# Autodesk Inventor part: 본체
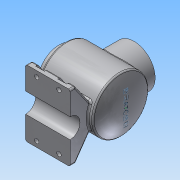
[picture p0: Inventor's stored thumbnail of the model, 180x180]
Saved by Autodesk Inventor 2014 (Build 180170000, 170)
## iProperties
Created: 2017-04
Part Number: 본체
Material: 알루미늄 6061
Document SubType Name: Modeling
Designer: NET
Density: 2.71 g/cm^3
Appearance: 알루미늄 - 평지
Author: NET
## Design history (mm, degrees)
sketch "스케치1"
  geometry: L1 (0, 0)-(0, 38); L2 (0, 38)-(12, 38); L3 (12, 38)-(12, 50); L4 (12, 50)-(110.934, 50); L5 (120, 5.651)-(120, 0); L6 (120, 0)-(0, 0); L7 (0, 27)-(22, 27); L8 (22, 27)-(22, 40); L9 (22, 40)-(104.104, 40); L10 (110, 5.651)-(110, 0); L11 (62, 73.5)-(62, 0); L12 (62, 73.5)-(100, 73.5); L13 (100, 73.5)-(100, 30.802); L14 (100, 30.802)-(62, 30.802); L15 (89, 73.5)-(89, 30.802); L16 (62, 0)-(62, -72); L17 (62, -72)-(102, -72); L18 (102, -72)-(102, -82); L19 (102, -82)-(62, -82); L20 (62, -82)-(62, -72); L21 (62, -72)-(22, -72); L22 (22, -72)-(22, -82); L23 (22, -82)-(62, -82); A1 r 113 centre (7, 5.651) between (119.859, 0) and (110.934, 50); A2 r 103 centre (7, 5.651) between (109.871, 0.5) and (104.104, 40); 1 further point
  constraints: 46 end point, 14 perpendicular, 7 parallel, 7 point on line, 6 point on circle, 2 centre point, 2 tangent, 2 vertical, 1 collinear, 1 midpoint
  dimensions: "d0" = 54 diameter of L7 L6; "d1" = 76 diameter of L2 L6; "d2" = 100 diameter of L4 L6; "d3" = 80 diameter of L9 L6; "d4" = 12 distance between parallel lines of L3 L1; "d5" = 22 distance between parallel lines of L8 L1; "d7" = 226 diameter of A1; "d8" = 10 radial gap between concentric circles of A2 A1; "d45" = 50 distance between parallel lines of L3 L11; "d46" = 23.5 distance between parallel lines of L4 L12; "d47" = 76 diameter of L13 L11; "d48" = 54 diameter of L15 L11; "d49" = 80 distance between parallel lines of L18 L22; "d50" = 10 distance between parallel lines of L21 L23; "d127" = 108 horizontal distance of L3.end L5.end; "d136" = 82 distance from line of L19 L10.end
revolve "회전1" stored, may be unused: angle "d14" = 90 deg
sketch "스케치3"
  geometry: C1 r 38 at (0, 0) reference; A1 r 32.5 centre (0, 0) between (0, 32.5) and (-32.5, 0); 2 further points
  constraints: 4 point on circle, 1 centre point, 1 coincident
  dimensions: "d28" = 65 diameter of A1
hole "구멍1" sketch "스케치3" at (-32.5, 0), (32.5, 0), (0, 32.5), (0, -32.5) diameter "d29" = 3.242; stored, may be unused: countersink angle "d33" = 90 deg, drill point angle "d35" = 118 deg; dims "d30" = 8, "d31" = 4, "d32" = 2, "d34" = 10
revolve "회전3" stored, may be unused: angle "d51" = 90 deg
extrude "돌출4" join sketch "스케치1" stored distance "d52" = 120; taper "d53" = 0 deg
sketch "스케치5"
  geometry: L1 (-120, 0)-(0, 0) reference; L2 (-120, 10)-(0, 10) reference; L3 (-120, 0)-(-120, 10) reference; L4 (-120, 10)-(-70.771, 44.47); L5 (-70.771, 44.47)-(-49.229, 44.47); L6 (-49.229, 44.47)-(0, 10); C1 r 18 at (-60, 0); 1 further point
  constraints: 6 end point, 1 centre point, 1 equal length, 1 midpoint, 1 perpendicular
  dimensions: "d54" = 55 deg angle of L3 L4; "d55" = 36 diameter of C1
extrude "돌출5" join sketch "스케치5" distance "d56" = 80; taper "d57" = 0 deg
extrude "돌출6" cut sketch "스케치5" distance "d58" = 80; taper "d59" = 0 deg
node "작업 평면1"
sketch "스케치6"
  geometry: L1 (40, 0)-(-40, 0) reference; L2 (-40, -78)-(-40, -120) reference; L3 (-40, 0)-(-40, -42) reference; L4 (40, 0)-(40, -42) reference; L5 (40, -78)-(40, -120) reference; L6 (-40, -120)-(40, -120) reference; L7 (-28, -10)-(-28, 0); L8 (-12, -10)-(-12, 0); L9 (12, -10)-(12, 0); L10 (28, -10)-(28, 0); L11 (12, -110)-(12, -120); L12 (28, -110)-(28, -120); L13 (-12, -110)-(-12, -120); L14 (-28, -110)-(-28, -120); L15 (-28, -120)-(-12, -120); L16 (12, -120)-(28, -120); L17 (12, 0)-(28, 0); L18 (-12, 0)-(-28, 0); A1 r 8 centre (-20, -10) between (-28, -10) and (-12, -10); A2 r 8 centre (20, -10) between (12, -10) and (28, -10); A3 r 8 centre (-20, -110) between (-12, -110) and (-28, -110); A4 r 8 centre (20, -110) between (12, -110) and (28, -110); 1 further point
  constraints: 24 end point, 8 point on circle, 8 point on line, 8 tangent, 5 perpendicular, 4 centre point, 4 collinear, 3 equal radius, 3 parallel
  dimensions: "d61" = 16 diameter of A1; "d62" = 10 distance from line of A1.centre L1; "d63" = 20 distance from line of L2 A3.centre; "d64" = 20 distance from line of A1.centre L3; "d65" = 20 distance from line of A2.centre L4; "d66" = 10 distance from line of L1 A2.centre; "d67" = 20 distance from line of L5 A4.centre; "d68" = 10 distance from line of L6 A4.centre; "d69" = 10 distance from line of L6 A3.centre
extrude "돌출7" cut sketch "스케치6" distance "d70" = 30; taper "d71" = 0 deg; dims "d125" = 4, "d126" = 0
hole "구멍3" diameter "d74" = 8; stored, may be unused: countersink angle "d78" = 90 deg, drill point angle "d80" = 118 deg; dims "d75" = 8, "d76" = 4, "d77" = 2, "d79" = 10, "d128" = 10, "d129" = 10
hole "구멍4" diameter "d83" = 8; stored, may be unused: countersink angle "d87" = 90 deg, drill point angle "d89" = 118 deg; dims "d84" = 8, "d85" = 4, "d86" = 2, "d88" = 10, "d130" = 10, "d131" = 10
hole "구멍5" diameter "d92" = 8; stored, may be unused: countersink angle "d96" = 90 deg, drill point angle "d98" = 118 deg; dims "d93" = 8, "d94" = 4, "d95" = 2, "d97" = 10, "d132" = 10, "d133" = 10
hole "구멍6" diameter "d101" = 8; stored, may be unused: countersink angle "d105" = 90 deg, drill point angle "d107" = 118 deg; dims "d102" = 8, "d103" = 4, "d104" = 2, "d106" = 10, "d134" = 10, "d135" = 10
sketch "스케치7"
  geometry: C1 r 38 at (0, 0) reference; A1 r 32.5 centre (0, 0) between (0, 32.5) and (0, -32.5); 3 further points
  constraints: 4 point on circle, 1 centre point, 1 coincident
  dimensions: "d108" = 65 diameter of A1
hole "구멍7" sketch "스케치7" at (32.5, 0), (0, 32.5), (0, -32.5), (-32.5, 0) diameter "d109" = 3.242; stored, may be unused: countersink angle "d113" = 90 deg, drill point angle "d115" = 118 deg; dims "d110" = 8, "d111" = 4, "d112" = 2, "d114" = 10
revolve "회전4" stored, may be unused: angle "d116" = 90 deg
revolve "회전5" stored, may be unused: angle "d117" = 90 deg
fillet "모깎기1" dims "d118" = 3
fillet "모깎기2" dims "d119" = 3
fillet "모깎기3" dims "d120" = 3
fillet "모깎기4" dims "d121" = 3
fillet "모깎기5" dims "d122" = 1
fillet "모깎기6" dims "d123" = 3
node "작업 평면3"
sketch "스케치9"
  geometry: 2 further points
  constraints: 1 coincident, 1 other
node "솔리드1"
other parameters: "d60" = 35 deg, "d124" = 120.5
